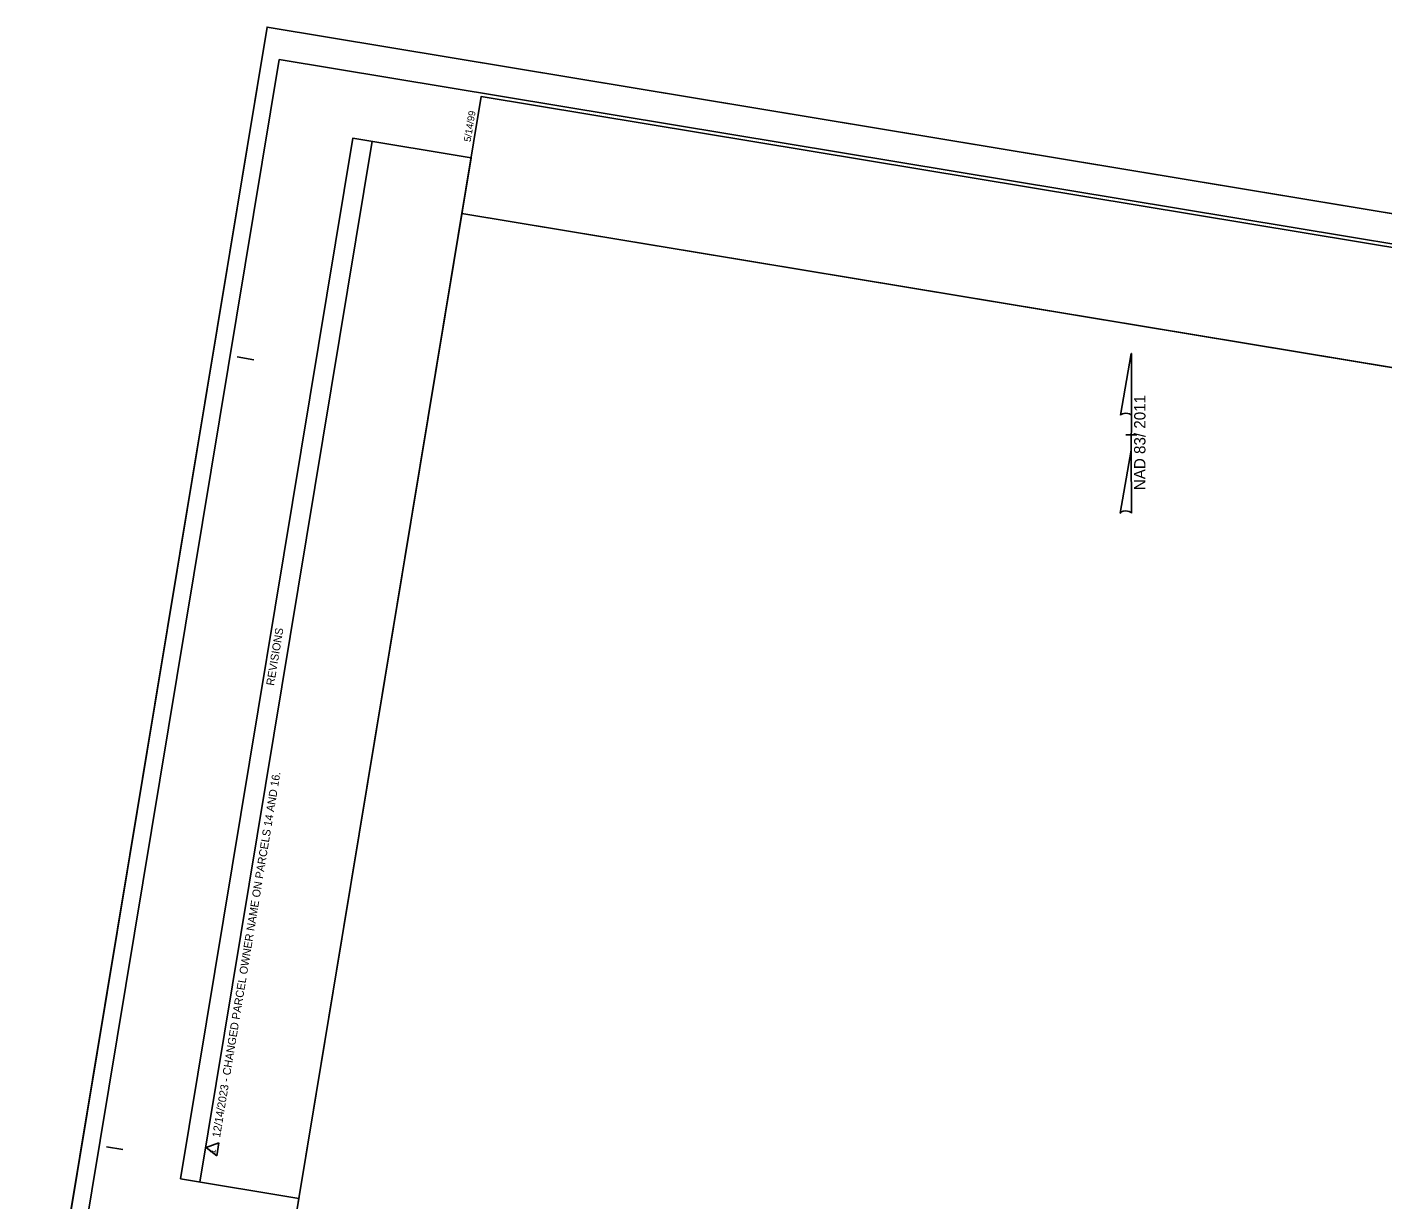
# Model space of a CAD drawing. Extents: x 2191153 to 2193185, y 85349 to 86740.
# Drawn here: x 2191153 to 2192169, y 85861 to 86740 of the extents above; entities that cross this region are included whole.
import ezdxf

# ---------------------------------------------------------------- set-up
doc = ezdxf.new("R2010")
doc.units = 0
for name, color, linetype in [('CTL Primary Horizontal Cogo Comment', 7, 'Continuous'), ('CTL Primary Horizontal Cogo Elevation', 7, 'Continuous'), ('CTL Primary Horizontal Cogo Number', 7, 'Continuous'), ('Exist Other Culture Sign', 7, 'Continuous'), ('Exist Property Iron Pin Cogo Number', 7, 'Continuous'), ('Exist Roads Curbs', 7, 'Continuous'), ('Exist Utilities Other Traffic Signal Box CELL', 7, 'Continuous'), ('Old_Level_6', 7, 'Continuous')]:
    doc.layers.add(name, color=color, linetype=linetype)

msp = doc.modelspace()

# ---------------------------------------------------------------- linework, layer by layer
at = {"layer": 'CTL Primary Horizontal Cogo Comment'}
for p, q in [((2191332.5, 86739.7), (2191152.6, 85654.5)), ((2192993.8, 86464.4), (2191332.5, 86739.7))]:
    msp.add_line(p, q, dxfattribs=at)
at = {"layer": 'CTL Primary Horizontal Cogo Elevation'}
msp.add_lwpolyline([(2192993.8, 86464.4), (2191332.5, 86739.7), (2191152.6, 85654.5), (2192814, 85379.2)], close=True, dxfattribs=at)
at = {"layer": 'CTL Primary Horizontal Cogo Number'}
msp.add_lwpolyline([(2192985.7, 86443), (2191341.6, 86715.4), (2191169.1, 85674.5), (2192813.2, 85402.1)], close=True, dxfattribs=at)
at = {"layer": 'Exist Other Culture Sign'}
for p, q in [((2191494.1, 86687.5), (2191494.1, 86687.5)), ((2191310.2, 86492.5), (2191322.6, 86490.4)), ((2191212.2, 85900.6), (2191224.5, 85898.5))]:
    msp.add_line(p, q, dxfattribs=at)
msp.add_lwpolyline([(2192972.9, 86442.5), (2191493.1, 86687.7), (2191321.5, 85651.8), (2192801.3, 85406.6)], close=True, dxfattribs=at)
at = {"layer": 'Exist Property Iron Pin Cogo Number'}
msp.add_line((2192434, 86441.8), (2191478.6, 86600.1), dxfattribs=at)
at = {"layer": 'Exist Roads Curbs'}
for p, q in [((2191972.2, 86448.8), (2191980.4, 86495.1)), ((2191980.5, 86495.1), (2191980.4, 86495.1)), ((2191980.5, 86495.1), (2191980.4, 86495.1)), ((2191980.5, 86495.1), (2191980.5, 86447.3)), ((2191980.4, 86422.5), (2191980.5, 86448.7)), ((2191980.5, 86447.3), (2191980.5, 86448.7)), ((2191976.5, 86434.1), (2191976.4, 86434.1)), ((2191976.5, 86434.1), (2191984.5, 86434.1)), ((2191980, 86434.1), (2191976.5, 86434.1)), ((2191980.4, 86422.5), (2191972.1, 86375.3)), ((2191980.5, 86375.5), (2191980.4, 86422.5))]:
    msp.add_line(p, q, dxfattribs=at)
for centre, start_param, end_param in [((2191976.3, 86448.3), 0.216388, 2.908219), ((2191976.3, 86375.1), 0.201328, 3.141593)]:
    msp.add_ellipse(centre, major_axis=(4.23, -0.03), ratio=0.461098, start_param=start_param, end_param=end_param, dxfattribs=at)
at = {"layer": 'Exist Utilities Other Traffic Signal Box CELL'}
msp.add_lwpolyline([(2192560.7, 86120.9), (2192910.1, 86063), (2192813.6, 85481), (2192809.4, 85455.3), (2192553.7, 85497.7), (2192545.6, 85449), (2191321.5, 85651.8), (2191478.6, 86600.1), (2192434, 86441.8)], close=True, dxfattribs=at)
at = {"layer": 'Old_Level_6'}
for p, q in [((2191282, 85874.1), (2191411.3, 86654.1)), ((2191286.9, 85900), (2191296.4, 85903.5)), ((2191294.8, 85893.7), (2191296.4, 85903.5)), ((2191294.8, 85893.7), (2191286.9, 85900))]:
    msp.add_line(p, q, dxfattribs=at)
msp.add_lwpolyline([(2191267.7, 85876.5), (2191396.9, 86656.5), (2191485.5, 86641.8), (2191356.3, 85861.8)], close=True, dxfattribs=at)

# ---------------------------------------------------------------- texts
at = {"layer": 'Exist Other Culture Sign'}
msp.add_text('5/14/99', height=5.25, rotation=80.5917, dxfattribs=at).set_placement((2191485.1, 86653.4))
at = {"layer": 'Exist Roads Curbs'}
msp.add_text('NAD 83/ 2011', height=8.5, rotation=89.9761, dxfattribs=at).set_placement((2191991, 86392.6))
at = {"layer": 'Old_Level_6'}
for s, height, p in [('REVISIONS', 6, (2191337.7, 86245.8)), ('  12/14/2023 - CHANGED PARCEL OWNER NAME ON PARCELS 14 AND 16.', 6, (2191296.5, 85902.7)), (' 1', 4.5, (2191293.3, 85893.5))]:
    msp.add_text(s, height=height, rotation=80.5917, dxfattribs=at).set_placement(p)

doc.saveas('drawing.dxf')
